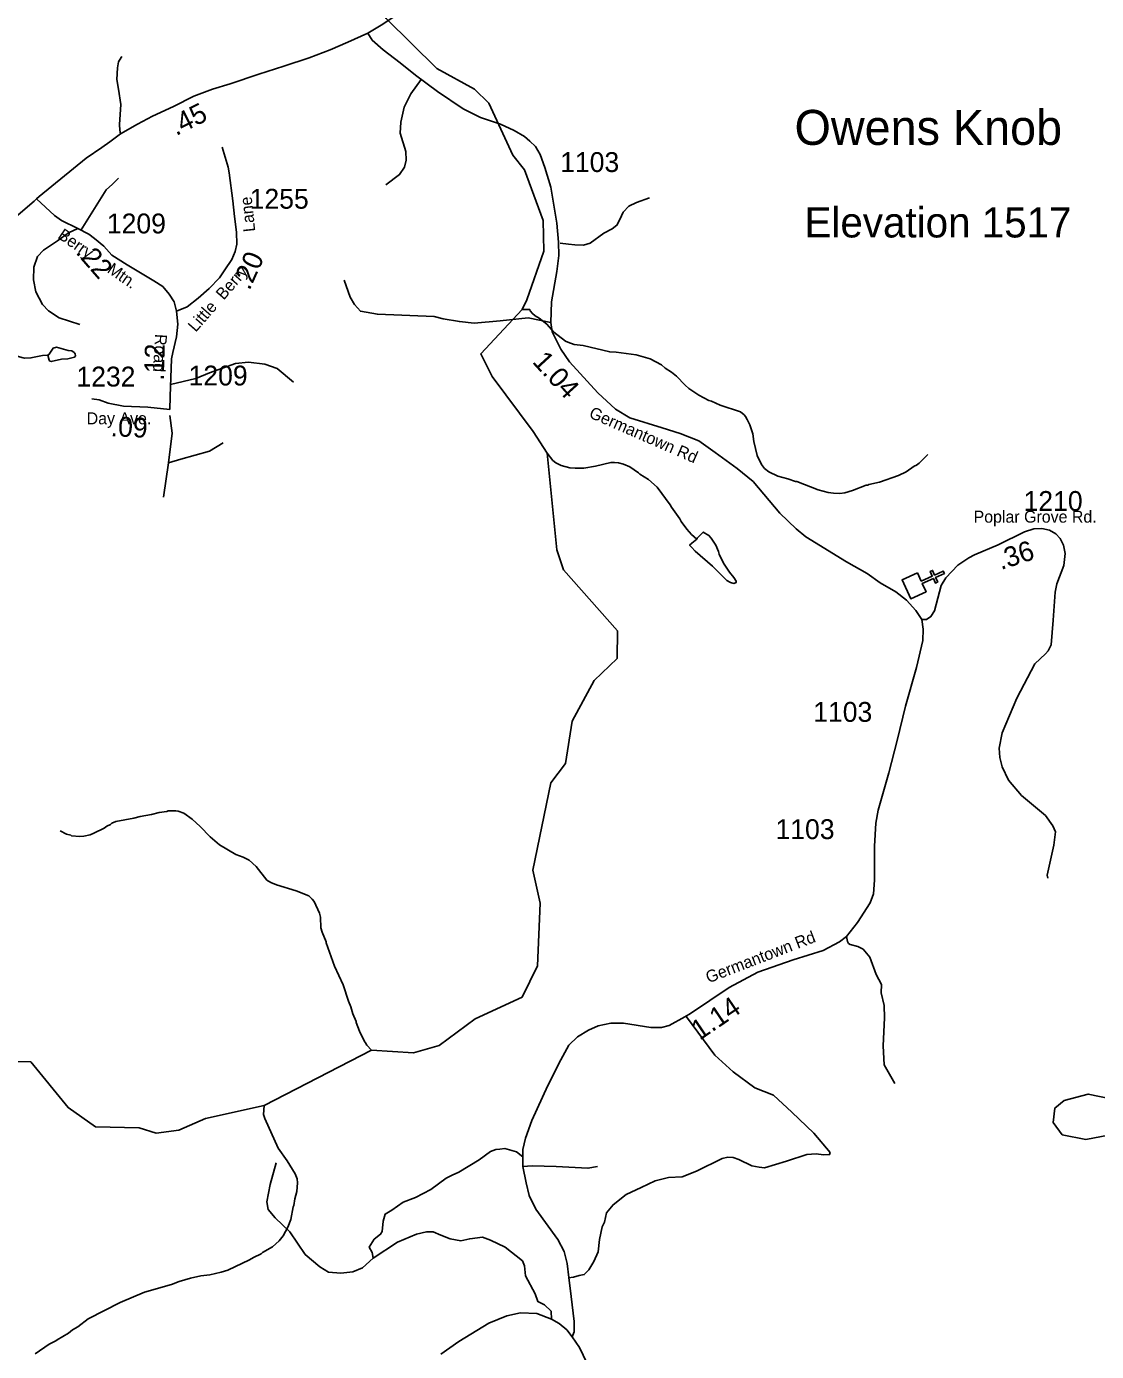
# Model space of a CAD drawing. Extents: x 1248224 to 1454986, y 825081 to 985870.
# Drawn here: x 1344200 to 1350937, y 865144 to 873483 of the extents above; entities that cross this region are included whole.
import ezdxf

# ---------------------------------------------------------------- set-up
doc = ezdxf.new("R2010")
doc.units = 0
for name, color, linetype in [('Exist Cultural Church CELL', 7, 'Continuous'), ('Exist Geographical Mountain Summit Elevation Number Label', 7, 'Continuous'), ('Exist Geographical Mountain Summit Label', 7, 'Continuous'), ('Exist Hydrographic Creek Single Shore', 7, 'Continuous'), ('Exist Hydrographic Misc Water Feature', 7, 'Continuous'), ('Exist Road Non-System Type 51', 7, 'Continuous'), ('Exist Road Primary NC Attributed', 7, 'Continuous'), ('Exist Road Primary NC Mileage Hundredths English Label', 7, 'Continuous'), ('Exist Road Secondary Mileage Hundredths English Label', 7, 'Continuous'), ('Exist Road Secondary Type 51 Attributed', 7, 'Continuous'), ('Exist Road Secondary Type 51 Label', 7, 'Continuous'), ('Exist Road Secondary Type 51 Number Label', 7, 'Continuous')]:
    doc.layers.add(name, color=color, linetype=linetype)

msp = doc.modelspace()

# ---------------------------------------------------------------- linework, layer by layer
at = {"layer": 'Exist Cultural Church CELL'}
msp.add_lwpolyline([(1349810.5, 870044.9), (1349834.1, 869993.1), (1349903.5, 870024.5), (1349890.3, 870053.6), (1349904.8, 870060.2), (1349918, 870031.1), (1349972.8, 870055.9), (1349979.4, 870041.3), (1349924.6, 870016.5), (1349937.9, 869987.4), (1349923.3, 869980.8), (1349910.1, 870009.9), (1349840.7, 869978.5), (1349864.5, 869925.9), (1349767.5, 869881.9), (1349713.6, 870000.9)], close=True, dxfattribs=at)
at = {"layer": 'Exist Hydrographic Creek Single Shore'}
msp.add_lwpolyline([(1351155.2, 866532.2), (1350870.2, 866478.7), (1350721.2, 866508.1), (1350664.2, 866584.8), (1350675.2, 866676.4), (1350734.2, 866724.5), (1350885.2, 866764.1), (1351109.2, 866716.9)], dxfattribs=at)
at = {"layer": 'Exist Hydrographic Misc Water Feature'}
for points in [[(1347322.2, 871702.5), (1347351.1, 871762.6), (1347458, 872069.1), (1347454, 872262.9), (1347336, 872580.4), (1347263, 872673.8), (1347112, 873001.9), (1347022.1, 873089), (1346783, 873218.5), (1346465.1, 873533.6), (1346400.1, 873643.1), (1346419, 873711.8), (1346487, 873766.2), (1346697, 873853.9), (1346988.1, 874199.3), (1347387, 874516.3), (1347542.1, 874656.1)], [(1344094.1, 866969.5), (1344227, 866966.9), (1344462.1, 866679.8), (1344635.1, 866558.1), (1344910.1, 866552.6), (1345017.1, 866517.6), (1345160.1, 866537.7), (1345328.1, 866609.9), (1345697.3, 866692), (1346372.2, 867041.6), (1346638.1, 867023.5), (1346798.1, 867069.5), (1347026.1, 867238.9), (1347321.2, 867374.1), (1347417.1, 867572.5), (1347434.1, 867966), (1347389.1, 868173.8), (1347501.1, 868722.9), (1347595.1, 868845.9), (1347635.1, 869111), (1347774.1, 869367.5), (1347919.1, 869505.7), (1347922.1, 869679.7), (1347581.1, 870064.1), (1347540.2, 870190.4), (1347479.3, 870799.1), (1347391.1, 870934.5), (1347132.1, 871281.2), (1347060, 871423.8), (1347322.2, 871702.5)], [(1349876.3, 870789.8), (1349821, 870735.1), (1349804.7, 870723.5), (1349788.5, 870715.9), (1349739.7, 870681), (1349691.2, 870658.2), (1349570.2, 870615.1), (1349503.9, 870600.7), (1349497.7, 870596.9), (1349487.8, 870597.1), (1349400.9, 870563.1), (1349352.7, 870548.3), (1349320.6, 870545.1), (1349280.6, 870546), (1349248.7, 870550.7), (1349185, 870568.3), (1349050.1, 870619.4), (1349042.1, 870619.6), (1348994.5, 870636.8), (1348930.9, 870654.3), (1348873.4, 870679.7), (1348848, 870702.3), (1348828.5, 870726.8), (1348801.8, 870783.4), (1348779.8, 870871.8), (1348772.9, 870920), (1348754.2, 870976.5), (1348738.9, 871010.9), (1348727.3, 871029.1), (1348719.6, 871039.3), (1348696, 871057.8), (1348568.9, 871100.9), (1348513.5, 871126.2), (1348497.6, 871130.5), (1348434.3, 871164), (1348371.3, 871205.6), (1348347.7, 871226.2), (1348292.9, 871283.4), (1348261.6, 871308.2), (1348222.1, 871333.1), (1348198.5, 871353.6), (1348127.4, 871391.3), (1348040, 871417.4), (1347912.4, 871434.5), (1347872.3, 871435.4), (1347705.2, 871475.4), (1347649.4, 871482.7), (1347609.6, 871495.7), (1347593.8, 871504), (1347521, 871559.8), (1347476.2, 871610.9), (1347429.1, 871648), (1347403.3, 871662.5), (1347385.7, 871677), (1347372.1, 871693.3), (1347370.2, 871701.4), (1347322.2, 871702.5)], [(1344334.9, 871414.7), (1344301.2, 871411.9), (1344228.8, 871397.6), (1344188.8, 871396.6), (1344149, 871407.5), (1344112.4, 871436.4)], [(1344334.9, 871414.7), (1344343.4, 871420.9), (1344368.2, 871458.3), (1344388.4, 871465.8), (1344461.9, 871444.1), (1344485.9, 871441.5), (1344501.6, 871431.1), (1344507.4, 871423), (1344509.2, 871411), (1344503, 871403.1), (1344460.8, 871392.1), (1344420.7, 871389), (1344356.3, 871374.6), (1344348.4, 871376.7), (1344342.5, 871382.9), (1344334.9, 871414.7)], [(1348420.2, 870257.9), (1348386.7, 870286.8), (1348357.5, 870319.5), (1348322.5, 870368.3), (1348315, 870384.5), (1348260.6, 870457.8), (1348252.9, 870473.9), (1348171.4, 870583.9), (1348116.6, 870633.1), (1348061.3, 870666.4), (1348053.4, 870674.6), (1347998.2, 870711.9), (1347958.7, 870728.9), (1347926.8, 870737.7), (1347902.9, 870740.2), (1347878.8, 870738.8), (1347782.3, 870717.1), (1347710, 870704.8), (1347654, 870704.2), (1347622.1, 870706.9), (1347566.3, 870720.2), (1347532.7, 870737.1), (1347515, 870751.4), (1347479.3, 870799.1)], [(1348420.2, 870257.9), (1348422.2, 870263.9), (1348461.3, 870301.1), (1348496.6, 870280.1), (1348512.2, 870263.8), (1348541.2, 870219.1), (1348558.3, 870178.7), (1348561.9, 870162.6), (1348588.7, 870106), (1348627.4, 870049), (1348654.7, 870016.4), (1348668.2, 869992.1), (1348667.9, 869984.1), (1348653.8, 869978.5), (1348633.9, 869984.9), (1348610.2, 869997.4), (1348520.2, 870087.6), (1348410.4, 870182.2), (1348386.9, 870206.8), (1348375.6, 870218.5), (1348389.5, 870230.7), (1348420.2, 870257.9)], [(1344413.4, 868421.6), (1344453, 868400.6), (1344478.8, 868394), (1344484.8, 868389.9), (1344536.7, 868384.6), (1344560.8, 868388.1), (1344600.9, 868397.1), (1344625.1, 868406.5), (1344689.9, 868439), (1344706.1, 868450.6), (1344730.4, 868462), (1344738.6, 868469.8), (1344762.8, 868479.2), (1344875.3, 868500.6), (1344915.6, 868511.6), (1344987.9, 868523.9), (1345036.2, 868536.8), (1345084.4, 868543.6), (1345092.5, 868547.4), (1345140.5, 868548.2), (1345156.4, 868545.9), (1345190.2, 868533.1), (1345243.3, 868493.8), (1345294.2, 868448.6), (1345356.8, 868383.2), (1345415.7, 868333.7), (1345518.3, 868273.3), (1345564, 868256.2), (1345601.6, 868237.3), (1345646.6, 868196.3), (1345714.7, 868110.7), (1345738.4, 868096.1), (1345774, 868081.2), (1345899.2, 868044.2), (1345978.6, 868012.3), (1346000.1, 867991.8), (1346011.7, 867975.6), (1346046.2, 867902.7), (1346051.6, 867878.6), (1346054, 867810.6), (1346061.4, 867784.4), (1346088, 867721.8), (1346087.9, 867715.8), (1346140.6, 867570.5), (1346193.9, 867451.3), (1346227.6, 867348.5), (1346242.8, 867314.1), (1346255.8, 867269.8), (1346276.7, 867221.3), (1346276.6, 867215.4), (1346297.3, 867160.9), (1346327.9, 867096.2), (1346335.7, 867088), (1346343.4, 867071.8), (1346372.2, 867041.6)], [(1344254.8, 865129.8), (1344344.2, 865191.6), (1344384.7, 865210.7), (1344392.8, 865218.5), (1344465.8, 865260.7), (1344490.3, 865280.1), (1344522.7, 865299.4), (1344587.9, 865349.8), (1344790.3, 865453), (1344943.8, 865517.4), (1345112.9, 865565.2), (1345161.4, 865584.1), (1345233.8, 865606.4), (1345298.2, 865620.9), (1345354.4, 865627.6), (1345426.8, 865643.8), (1345467.1, 865656.8), (1345604.6, 865721.6), (1345628.9, 865737), (1345677.5, 865759.8), (1345685.7, 865767.6), (1345748.5, 865804.1), (1345791.3, 865841.1), (1345816.1, 865872.5), (1345845.3, 865927.8), (1345864.4, 865975.3), (1345880.2, 866054.9), (1345884.4, 866062.9), (1345889.3, 866104.7), (1345902.3, 866150.5), (1345907.6, 866206.2), (1345904.2, 866230.3), (1345892.9, 866262.6), (1345842.7, 866343.8), (1345784.5, 866425.2), (1345700.7, 866611.1), (1345693.3, 866635.3), (1345697.3, 866692)]]:
    msp.add_lwpolyline(points, dxfattribs=at)
at = {"layer": 'Exist Road Non-System Type 51'}
for p, q in [((1345470.4, 872597.8), (1345431.5, 872724.6)), ((1345095, 870737), (1345063.7, 870521.8))]:
    msp.add_line(p, q, dxfattribs=at)
for points in [[(1344800.9, 873293.7), (1344796.3, 873289), (1344779.5, 873260.5), (1344772.6, 873222.5), (1344768.4, 873150.5), (1344779.5, 873089.5), (1344794.9, 872991.8), (1344789.3, 872929.3), (1344785.1, 872865.6), (1344787.9, 872831.6), (1344792.1, 872807.2)], [(1346463.8, 872487.6), (1346549.2, 872551.7), (1346579.5, 872598), (1346590.2, 872642.5), (1346588.4, 872695.9), (1346552.8, 872811.6), (1346558.1, 872881.1), (1346577.7, 872975.4), (1346620.4, 873059.1), (1346686.2, 873149.9)], [(1344545.4, 872202.8), (1344702.6, 872455.4), (1344742.9, 872491.9), (1344779.4, 872528.5)], [(1347559.8, 872119), (1347613.1, 872113.7), (1347652.3, 872108.4), (1347707.4, 872106.6), (1347750.1, 872120.8), (1347835.5, 872183.1), (1347888.9, 872209.8), (1347917.4, 872233), (1347936.9, 872268.6), (1347956.5, 872314.9), (1347993.9, 872352.3), (1348041.9, 872375.4), (1348123.7, 872405.7)], [(1344535.5, 871607.5), (1344406.6, 871649.7), (1344338.7, 871694.2), (1344301.2, 871734.1), (1344259, 871813.8), (1344245, 871888.8), (1344247.3, 871968.5), (1344270.7, 872036.5), (1344308.2, 872076.3), (1344394.9, 872134.9), (1344465.2, 872184.2), (1344523.2, 872211.2)], [(1346200.4, 871886.5), (1346237.6, 871779.4), (1346265.5, 871732.8), (1346302.7, 871690.9), (1346409.7, 871672.3), (1346767.9, 871658.4), (1346823.7, 871644.4), (1346926.1, 871625.8), (1347019.1, 871616.5), (1347181.9, 871630.4), (1347358.7, 871649), (1347500.8, 871620.5)], [(1345106.7, 871229.9), (1345267, 871269), (1345353, 871304.2), (1345517.2, 871362.9), (1345599.3, 871370.7), (1345700.9, 871359), (1345779.1, 871331.6), (1345880.7, 871245.5)], [(1345102.8, 871034.3), (1345118.5, 870924.8), (1345095, 870737)], [(1345095, 870737), (1345173.2, 870760.5), (1345353, 870811.3), (1345439, 870862.2)], [(1350615.4, 869535.8), (1350548.3, 869473), (1350436.6, 869255.8), (1350343.6, 869038.5), (1350325, 868942.3), (1350328.1, 868883.4), (1350343.6, 868824.4), (1350383.9, 868740.6), (1350464.5, 868644.4), (1350616.5, 868517.2), (1350663, 868453.1), (1350678.5, 868415.8), (1350669.2, 868332), (1350625.7, 868142.7), (1350631.2, 868122.9)], [(1349363.5, 867757.1), (1349370, 867725.2), (1349376.2, 867712.8), (1349385.5, 867706.6), (1349435.1, 867694.2), (1349469.2, 867675.6), (1349509.5, 867625.9), (1349549.9, 867517.3), (1349584, 867455.2), (1349580.9, 867402.5), (1349599.5, 867321.8), (1349602.6, 867244.2), (1349593.3, 867067.3), (1349599.5, 866949.4), (1349667.7, 866831.5)], [(1348355.8, 867250.9), (1348534.7, 867008.8), (1348648.8, 866904.8), (1348786.8, 866804.2), (1348902.7, 866758.2), (1349018.5, 866650.7), (1349158.2, 866519.5), (1349260.4, 866397.6), (1349257, 866383.9), (1349219.5, 866382.2), (1349171.8, 866389.1), (1349113.9, 866383.9), (1348986.1, 866341.3), (1348846.4, 866300.4)], [(1347325.4, 866369), (1347286, 866400.1), (1347211.6, 866421.8), (1347180.6, 866418.7), (1347155.7, 866415.6), (1347121.6, 866403.2), (1347050.3, 866350.5), (1346923.2, 866272.9), (1346879.8, 866254.3), (1346842.5, 866235.6), (1346746.4, 866164.3), (1346650.3, 866114.6), (1346572.7, 866083.6), (1346501.4, 866033.9), (1346458, 866009.1), (1346445.6, 865965.6), (1346439.4, 865900.5), (1346430.1, 865881.9), (1346389.8, 865850.8), (1346358.8, 865801.2), (1346377.4, 865767), (1346383.6, 865732.9)], [(1347613.1, 865608.2), (1347643.7, 865611.6), (1347681.2, 865621.9), (1347711.9, 865628.7), (1347740.8, 865659.4), (1347773.2, 865710.5), (1347798.8, 865771.9), (1347807.3, 865850.3), (1347826, 865928.7), (1347839.6, 865959.4), (1347853.3, 866017.4), (1347894.1, 866068.5), (1347975.9, 866131.6), (1348069.6, 866175.9), (1348158.2, 866218.6), (1348243.4, 866239), (1348328.6, 866244.1), (1348418.8, 866279.1), (1348580.7, 866359.2), (1348616.5, 866367.7), (1348650.5, 866366), (1348686.3, 866352.4), (1348766.4, 866313.2), (1348814.1, 866304.7), (1348846.4, 866300.4)], [(1345772.4, 866332.4), (1345735.2, 866195.9), (1345713.5, 866087.3), (1345722.8, 866037.6), (1345766.2, 865984.9), (1345859.2, 865898), (1345955.3, 865755.2), (1346048.4, 865677.6), (1346101.1, 865643.5), (1346178.6, 865637.3), (1346256.1, 865646.6), (1346315.1, 865671.4), (1346383.6, 865732.9)], [(1347325.2, 866309.8), (1347384.8, 866313.2), (1347534.7, 866308.1), (1347735.7, 866297.8), (1347795.3, 866308.1)], [(1346383.6, 865732.9), (1346535.5, 865832.2), (1346656.5, 865881.9), (1346718.5, 865897.4), (1346761.9, 865897.4), (1346808.4, 865875.6), (1346867.3, 865853.9), (1346935.6, 865841.5), (1346991.4, 865853.9), (1347072, 865863.2), (1347121.6, 865844.6), (1347214.7, 865801.2), (1347323.2, 865714.3), (1347335.6, 865683.2), (1347341.8, 865621.2), (1347403.8, 865506.4), (1347419.3, 865459.8), (1347462.8, 865438.1), (1347503.1, 865397.7), (1347505.1, 865348.1)]]:
    msp.add_lwpolyline(points, dxfattribs=at)
at = {"layer": 'Exist Road Primary NC Attributed'}
for points in [[(1346348.7, 873442.3), (1346443.8, 873497.7), (1346514.7, 873546.5), (1346606, 873617.5), (1346681, 873682.4), (1346800.7, 873802.2), (1346898, 873909.8), (1346997.4, 874013.3), (1347068.4, 874086.3), (1347147.5, 874163.5), (1347210.3, 874220.3), (1347267.1, 874254.8), (1347363.9, 874330.8), (1347451.1, 874387.7), (1347526.3, 874435.8)], [(1344264.2, 872398.1), (1344280.5, 872412.8), (1344576.1, 872654.6), (1344674, 872722.4), (1344725.7, 872757.7), (1344792.1, 872807.2), (1344899.1, 872869), (1344992.8, 872919.2), (1345125.7, 872980.2), (1345254.3, 873044), (1345371.1, 873088.1), (1345483, 873123.4), (1345663.4, 873183.1), (1345820.7, 873234), (1345980.2, 873285.6), (1346113, 873335.8), (1346223.5, 873384.6), (1346348.7, 873442.3)], [(1343775.9, 872024.4), (1343932.1, 872127.9), (1344074, 872235.2), (1344247.8, 872383.4), (1344264.2, 872398.1)]]:
    msp.add_lwpolyline(points, dxfattribs=at)
at = {"layer": 'Exist Road Secondary Type 51 Attributed'}
for points in [[(1349836.7, 869751), (1349799.5, 869807.5), (1349740.1, 869872.9), (1349674.8, 869926.4), (1349575.3, 869982.9), (1349493.3, 870040), (1349363.9, 870113.7), (1349106.6, 870272.5), (1349046.1, 870322.3), (1348942.7, 870419.8), (1348775.5, 870620.1), (1348675.7, 870700.9), (1348535.6, 870802), (1348433.4, 870875.1), (1348317, 870922.6), (1348203, 870958.3), (1347998.7, 871020.1), (1347908.4, 871074.8), (1347796.7, 871177), (1347618.5, 871372), (1347563.9, 871452.8), (1347510.1, 871562.3), (1347500.8, 871620.5), (1347506.6, 871749.9), (1347540.4, 871941.5), (1347552, 872042.9), (1347549.7, 872126.8), (1347539.2, 872245.9), (1347501.9, 872472), (1347464.7, 872596.7), (1347434.6, 872678.8), (1347405.5, 872727.7), (1347370.5, 872761.5), (1347336.8, 872790.7), (1347270.4, 872828), (1347185.4, 872868.7), (1347058.5, 872910.7), (1346949.7, 872966), (1346789, 873074.4), (1346649.3, 873178.1), (1346552.6, 873253.9), (1346447.1, 873337.2), (1346377.3, 873397.8), (1346348.7, 873442.3)], [(1345145.3, 871690.9), (1345212.4, 871719.1), (1345282.4, 871774.1), (1345349.9, 871834.1), (1345414.9, 871901.7), (1345449.9, 871951.7), (1345492.4, 872016.7), (1345514.9, 872066.8), (1345524.9, 872114.3), (1345522.4, 872189.3), (1345509.9, 872286.9), (1345499.9, 872387), (1345477.4, 872562.1), (1345470.4, 872597.8)], [(1344264.2, 872398.1), (1344376.5, 872293), (1344421.1, 872263.3), (1344523.2, 872211.2), (1344593.8, 872175.9), (1344629.1, 872149.9), (1344686.6, 872101.6), (1344736.8, 872044), (1344835.2, 871982.6), (1345002.3, 871882.3), (1345058, 871847), (1345098.9, 871798.7), (1345130.4, 871750.3), (1345145.3, 871690.9)], [(1345145.3, 871690.9), (1345152.8, 871610.3), (1345145.7, 871529.4), (1345122, 871431.9), (1345112.5, 871391.5), (1345105.3, 871153.8), (1345103, 871072.9)], [(1345103, 871072.9), (1344965.2, 871087.2), (1344810.7, 871094.3), (1344715.7, 871113.4), (1344658.7, 871134.7), (1344611.2, 871139.5)], [(1349836.7, 869751), (1349866.7, 869750.5), (1349895, 869769.4), (1349916.6, 869805.9), (1349959.8, 869965.3), (1349988.2, 870013.9), (1350065.1, 870093.6), (1350133.4, 870140.3), (1350169.8, 870157.8), (1350318.3, 870221.3), (1350484.3, 870302.4), (1350542.4, 870321.3), (1350592.3, 870324), (1350640.9, 870313.2), (1350681.4, 870290.2), (1350708.4, 870260.5), (1350728.6, 870220), (1350739.4, 870165.9), (1350731.3, 870091.6), (1350688.1, 869975.5), (1350677.3, 869922.8), (1350665.2, 869747.2), (1350652.9, 869592.7), (1350634, 869553.6), (1350615.4, 869535.8)], [(1347635.1, 865235.8), (1347648.6, 865268.2), (1347648.6, 865333), (1347629.7, 865489.7), (1347616, 865609.5), (1347605.4, 865697.8), (1347586.5, 865773.4), (1347546.7, 865850.3), (1347406.3, 866039.4), (1347365.8, 866125.9), (1347346.9, 866206.9), (1347325.4, 866309.6), (1347325.4, 866415), (1347341.6, 866487.9), (1347382, 866598.7), (1347483.4, 866818.8), (1347564.4, 866980.9), (1347615.7, 867072.7), (1347669.7, 867124.1), (1347739.8, 867167.3), (1347799.2, 867194.3), (1347880.2, 867210.5), (1347958.5, 867210.5), (1348131.3, 867183.5), (1348198.8, 867183.5), (1348247.4, 867197), (1348344.5, 867251.1), (1348381.4, 867271.4), (1348624.4, 867436.2), (1348805.3, 867530.8), (1349026.6, 867609.1), (1349215.6, 867668.6), (1349318.2, 867722.6), (1349363.5, 867757.1), (1349433.6, 867843.5), (1349511.9, 867967.8), (1349533.5, 868024.6), (1349538.9, 868111), (1349538.9, 868324.4), (1349547, 868470.3), (1349563.2, 868551.4), (1349630.5, 868787.3), (1349681.8, 868990), (1349735.8, 869206.1), (1349803.3, 869449.2), (1349843.8, 869619.4), (1349846.5, 869689.7), (1349836.7, 869751)], [(1346809.1, 865128.1), (1346921.8, 865207.3), (1347111.2, 865322.8), (1347224, 865369.9), (1347311.5, 865388.5), (1347414.1, 865383.4), (1347505.1, 865348.1), (1347553.8, 865321.1), (1347601.9, 865280.9), (1347635.1, 865235.8)], [(1347727.8, 865072.9), (1347682.7, 865169.8), (1347635.1, 865235.8)]]:
    msp.add_lwpolyline(points, dxfattribs=at)

# ---------------------------------------------------------------- texts
at = {"layer": 'Exist Geographical Mountain Summit Elevation Number Label'}
msp.add_text('Elevation 1517', height=190, dxfattribs=at).set_placement((1349099, 872155.7))
at = {"layer": 'Exist Geographical Mountain Summit Label'}
msp.add_text('Owens Knob', height=220, dxfattribs=at).set_placement((1349036.1, 872738.4))
at = {"layer": 'Exist Road Primary NC Mileage Hundredths English Label'}
msp.add_text('.45', height=125, rotation=26.36821, dxfattribs=at).set_placement((1345141.5, 872793.6))
at = {"layer": 'Exist Road Secondary Mileage Hundredths English Label'}
for s, rotation, p in [('.22', 311.03206, (1344505.7, 872060.2)), ('.20', 65.78917, (1345604.2, 871817.7)), ('.12', 88.2831, (1345064.7, 871253)), ('1.04', 312.42471, (1347380.1, 871370.5)), ('.09', 357.35518, (1344728.5, 870905.5)), ('.36', 18.04762, (1350335, 870062)), ('1.14', 34.14949, (1348439.2, 867100.1))]:
    msp.add_text(s, height=125, rotation=rotation, dxfattribs=at).set_placement(p)
at = {"layer": 'Exist Road Secondary Type 51 Label'}
for s, rotation, p in [(' Lane', 96.07267, (1345644.2, 872166.6)), ('Berry     Mtn.', 325.3153, (1344391.8, 872155.3)), ('Little  Berry', 48.92836, (1345266, 871555.8)), ('Road', 266.63688, (1345010.7, 871549.7)), ('Germantown Rd', 336.40596, (1347736.7, 871025.2)), ('Germantown Rd', 21.10473, (1348494.4, 867461.3))]:
    msp.add_text(s, height=75, rotation=rotation, dxfattribs=at).set_placement(p)
for s, p in [('Day Ave.', (1344579.4, 870979.8)), ('Poplar Grove Rd.', (1350163.6, 870360.8))]:
    msp.add_text(s, height=75, dxfattribs=at).set_placement(p)
at = {"layer": 'Exist Road Secondary Type 51 Number Label'}
for s, p in [('1103', (1347560.4, 872567.6)), ('1255', (1345605.6, 872336.7)), ('1209', (1344706.5, 872181.2)), ('1232', (1344514.8, 871217.7)), ('1209', (1345221.1, 871224.2)), ('1210', (1350478.3, 870434.6)), ('1103', (1349153.7, 869107.3)), ('1103', (1348916.3, 868369.3))]:
    msp.add_text(s, height=125, dxfattribs=at).set_placement(p)

doc.saveas('drawing.dxf')
